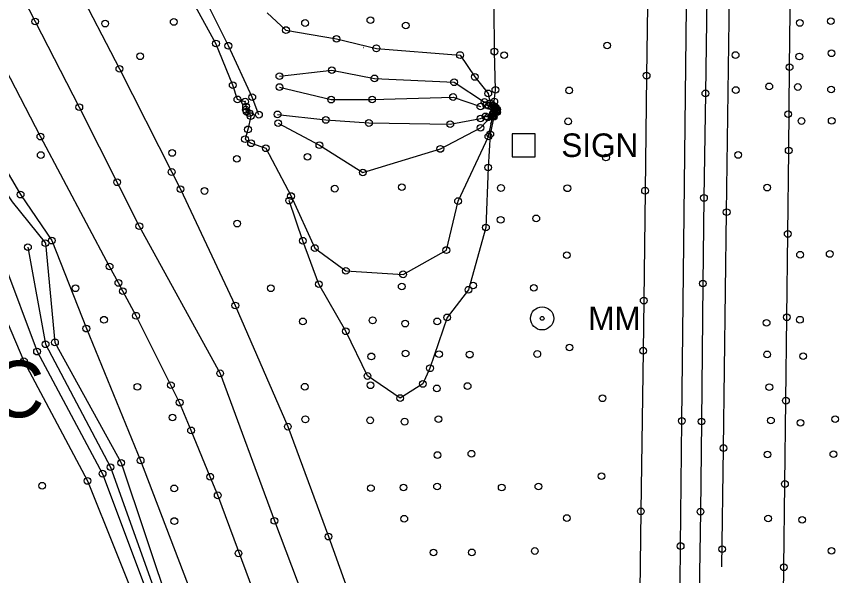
# Model space of a CAD drawing. Extents: x 20503438 to 20508873, y 7964251 to 7984667.
# Drawn here: x 20506434.7 to 20506679.2, y 7969674.2 to 7969840.4 of the extents above; entities that cross this region are included whole.
import ezdxf

# ---------------------------------------------------------------- set-up
doc = ezdxf.new("R2010")
doc.units = 0
for name, color, linetype in [('SurBreakLine', 7, 'Continuous'), ('SurConcreteSlab', 7, 'Continuous'), ('SurDrainageArrowDown', 7, 'Continuous'), ('SurDrainageArrowUp', 7, 'Continuous'), ('SurEdgeRoadPaved', 7, 'Continuous'), ('SurEdgeShoulderPaved', 7, 'Continuous'), ('SurGuardRailCable', 7, 'Continuous'), ('SurPointsNonDTM', 7, 'Continuous'), ('SurRoadPoints', 7, 'Continuous'), ('SurSurveyPoints', 7, 'Continuous'), ('SurTopOfWater', 7, 'Continuous'), ('SurTxtDrainage', 7, 'Continuous')]:
    doc.layers.add(name, color=color, linetype=linetype)

msp = doc.modelspace()

# ---------------------------------------------------------------- linework, layer by layer
at = {"layer": 'SurBreakLine'}
for points in [[(20506630.22, 7970500.51), (20506629.94, 7970458.31), (20506629.34, 7970411.54), (20506628.69, 7970380.29), (20506628.52, 7970349.87), (20506627.74, 7970284.03), (20506627.47, 7970249.09), (20506626.82, 7970216.67), (20506626.3, 7970146.74), (20506624.57, 7970007.29), (20506624.05, 7969973.48), (20506623.87, 7969953.25), (20506623.51, 7969921.12), (20506622.74, 7969871.31), (20506622.11, 7969822.83), (20506621.64, 7969788.61), (20506621.25, 7969755.93), (20506621.07, 7969741.02), (20506620.4, 7969693.27), (20506619.78, 7969645.95), (20506618.53, 7969549.76), (20506618.14, 7969523.36), (20506617.67, 7969481.03)], [(20506055.68, 7970391.77), (20506077.75, 7970359.75), (20506108.69, 7970301.09), (20506132.04, 7970256.55), (20506165.25, 7970205.48), (20506192.45, 7970157.41), (20506224.46, 7970101.44), (20506248.25, 7970061.27), (20506293.41, 7969992.66), (20506326.25, 7969942.44), (20506365.51, 7969880.7), (20506394.3, 7969832.14), (20506425.75, 7969780.09), (20506430.79, 7969767.57), (20506440.81, 7969740.77), (20506460.31, 7969704.46), (20506476.26, 7969661.89), (20506493.48, 7969607.85), (20506507.96, 7969563.39)], [(20506265.17, 7970071.99), (20506309.01, 7970002.39), (20506340.2, 7969952.07), (20506378, 7969886.15), (20506406.73, 7969836.94), (20506435.92, 7969787.45), (20506445.2, 7969773.78), (20506455.48, 7969747.6), (20506471.62, 7969708.42), (20506487.81, 7969665.88), (20506504.3, 7969609.54), (20506517.07, 7969565.09), (20506530.55, 7969501.87), (20506539.77, 7969458.14)], [(20506259.31, 7970069.25), (20506303.96, 7969999.09), (20506335.37, 7969948.79), (20506372.37, 7969884.24), (20506399.91, 7969834.73), (20506433.45, 7969785.26), (20506443.29, 7969773.02), (20506446.14, 7969743.51), (20506465.85, 7969707.69), (20506480.64, 7969663.58), (20506499.73, 7969608.5), (20506514.68, 7969564.41), (20506526.38, 7969501.4), (20506535.77, 7969458.35)], [(20506576.47, 7969813.92), (20506576.81, 7969815.09), (20506577.14, 7969818.61), (20506576.83, 7969829.97), (20506576.75, 7969843.33), (20506575.3, 7969863.86), (20506578.05, 7969884.56), (20506578.11, 7969925.71), (20506579.5, 7969969.66), (20506580.94, 7970015.91), (20506579.56, 7970061.86)], [(20506245.46, 7970059.26), (20506289.42, 7969989.86), (20506322.08, 7969939.84), (20506362.1, 7969878.45), (20506391.2, 7969829.89), (20506418.64, 7969776.17), (20506425.78, 7969763.92), (20506436.91, 7969737.91), (20506455.83, 7969702.3), (20506472.72, 7969660.29), (20506490.33, 7969606.63), (20506502.81, 7969561.31), (20506518.36, 7969500.09), (20506526.15, 7969455.03)], [(20506502.97, 7969813.65), (20506502.68, 7969815.08), (20506500.4, 7969815.76), (20506499.02, 7969820), (20506494.03, 7969832.4), (20506486.84, 7969845.43)], [(20506509.22, 7969841.54), (20506514.85, 7969836.38), (20506529.87, 7969833.76), (20506541.73, 7969830.94), (20506566.61, 7969828.95), (20506571.04, 7969822.43), (20506575.01, 7969817.54), (20506575.59, 7969814.64), (20506576.47, 7969813.92)], [(20506512.89, 7969822.68), (20506528.49, 7969824.45), (20506541.15, 7969822.01), (20506564.85, 7969820.86), (20506573.91, 7969814.98), (20506575.59, 7969814.64)], [(20506512.53, 7969808.7), (20506524.78, 7969802.14), (20506537.72, 7969794.01), (20506560.76, 7969801.03), (20506572.71, 7969807.3), (20506576.64, 7969811.43), (20506577.65, 7969811.98), (20506577.62, 7969812.72), (20506577.19, 7969813.47), (20506576.47, 7969813.92)], [(20506503.95, 7969811.65), (20506504.35, 7969810.81), (20506503.55, 7969806.83), (20506502.67, 7969803.92), (20506504.46, 7969802.72), (20506508.87, 7969801.23), (20506516.35, 7969787.02), (20506523.4, 7969771.55), (20506532.68, 7969764.79), (20506549.67, 7969763.74), (20506562.55, 7969770.96), (20506566.04, 7969785.52), (20506575.06, 7969804.72), (20506576.35, 7969810.79), (20506576.64, 7969811.43)], [(20506512.36, 7969811.29), (20506526.72, 7969809.66), (20506539.52, 7969808.75), (20506563.72, 7969808.41), (20506572.72, 7969810.1), (20506574.23, 7969810.71)], [(20506576.64, 7969811.43), (20506576.68, 7969810.56), (20506575.61, 7969805.43), (20506575, 7969795.51), (20506574.32, 7969777.67), (20506569.14, 7969759.17), (20506562.79, 7969750.93), (20506557.68, 7969735.8), (20506555.54, 7969731.15), (20506548.82, 7969726.94), (20506539.09, 7969733.51), (20506532.67, 7969746.81), (20506524.63, 7969760.83), (20506519.88, 7969773.73), (20506515.8, 7969785.66)]]:
    msp.add_lwpolyline(points, dxfattribs=at)
at = {"layer": 'SurConcreteSlab'}
for points in [[(20506312.48, 7970084.37), (20506343.03, 7970026.25), (20506361.37, 7969990.21), (20506379.77, 7969955.07), (20506398.31, 7969920.35), (20506410.28, 7969897), (20506440.24, 7969838.92), (20506453.38, 7969813.47), (20506471.23, 7969778.05), (20506495.26, 7969734.3), (20506511.4, 7969690.45), (20506526.3, 7969651.11), (20506541.85, 7969602.36), (20506553.45, 7969551.94), (20506564.49, 7969514.44), (20506574.01, 7969461.11)], [(20506502.97, 7969813.65), (20506502.9, 7969812.7), (20506503.12, 7969812.13), (20506503.95, 7969811.65)]]:
    msp.add_lwpolyline(points, dxfattribs=at)
msp.add_lwpolyline([(20506574.23, 7969810.71), (20506576.62, 7969811.64), (20506577.29, 7969812.12), (20506577.07, 7969813.1), (20506576.06, 7969813.56), (20506574.42, 7969814.11), (20506575.09, 7969813.89), (20506576.82, 7969813.61), (20506577.38, 7969813), (20506577.49, 7969812.41), (20506577.24, 7969811.87), (20506576.43, 7969811.46), (20506574.91, 7969810.43)], close=True, dxfattribs=at)
at = {"layer": 'SurDrainageArrowDown'}
msp.add_lwpolyline([(20506660.27, 7969478.45), (20506660.63, 7969503.23), (20506660.96, 7969528), (20506661.29, 7969552.77), (20506661.62, 7969577.54), (20506661.94, 7969602.32), (20506662.27, 7969627.09), (20506662.6, 7969651.86), (20506662.93, 7969676.63), (20506663.25, 7969701.4), (20506663.54, 7969726.18), (20506663.82, 7969750.97), (20506664.09, 7969775.76), (20506664.37, 7969800.55), (20506664.64, 7969825.33), (20506664.92, 7969850.12), (20506665.19, 7969874.91), (20506665.47, 7969899.7), (20506665.74, 7969924.48), (20506666.29, 7969949.48), (20506666.84, 7969974.47), (20506667.39, 7969999.46), (20506667.92, 7970023.56)], dxfattribs=at)
at = {"layer": 'SurDrainageArrowUp'}
for points in [[(20506506.8, 7969811.22), (20506504.83, 7969816.42), (20506497.71, 7969831.72), (20506490.19, 7969846.9), (20506487, 7969862.95), (20506473.82, 7969880.15), (20506462.67, 7969902.49), (20506454.28, 7969923.38)], [(20506512.92, 7969819.43), (20506528.29, 7969815.7), (20506540.49, 7969815.71), (20506564.54, 7969816.47), (20506572.67, 7969813.63)], [(20506438.1, 7969771.83), (20506443.35, 7969742.94), (20506462.68, 7969706.4), (20506478.32, 7969662.6), (20506496.28, 7969609.97), (20506512.32, 7969564.26), (20506521.33, 7969501.72), (20506530.41, 7969455.42), (20506542.25, 7969371.11), (20506545.39, 7969325.12), (20506547.61, 7969281.18), (20506550.51, 7969229.55), (20506551.89, 7969191.24), (20506551.28, 7969123.71), (20506552.43, 7969055.04)]]:
    msp.add_lwpolyline(points, dxfattribs=at)
at = {"layer": 'SurEdgeRoadPaved'}
for points in [[(20506631.32, 7969619.45), (20506631.68, 7969642.79), (20506632.12, 7969671.61), (20506632.23, 7969682.94), (20506632.59, 7969720.14), (20506634, 7969843.3), (20506635.85, 7969961.58), (20506636.59, 7970028.9), (20506637.95, 7970121.57), (20506639.37, 7970242.27), (20506639.5, 7970278.6), (20506640.61, 7970371.42), (20506641.91, 7970469.55), (20506641.82, 7970500.36)], [(20506352.99, 7970040.84), (20506374.32, 7969999.65), (20506390.57, 7969968.92), (20506409.06, 7969933.38), (20506428.12, 7969896.18), (20506452.11, 7969850.37), (20506465.31, 7969824.83), (20506480.86, 7969794.17), (20506483.46, 7969789.06), (20506499.78, 7969754.47), (20506515.4, 7969718.45), (20506527.51, 7969685.76), (20506540.05, 7969650.65), (20506551.47, 7969616.02), (20506560.28, 7969585.76), (20506569.39, 7969550.43), (20506574.82, 7969528.04), (20506577.29, 7969513.59), (20506582.94, 7969483.55), (20506590.54, 7969483.63), (20506595.61, 7969483.68)]]:
    msp.add_lwpolyline(points, dxfattribs=at)
at = {"layer": 'SurEdgeShoulderPaved'}
for points in [[(20506648.62, 7970500.27), (20506647.27, 7970459.01), (20506646.9, 7970417.14), (20506644.76, 7970214.42), (20506643.68, 7970120.75), (20506642.88, 7970059), (20506642.28, 7970020.9), (20506641.72, 7969970.09), (20506641.45, 7969947.33), (20506640.93, 7969913.12), (20506640.56, 7969882.02), (20506639.59, 7969817.55), (20506639.17, 7969786.45), (20506638.82, 7969761), (20506638.43, 7969719.99), (20506638.13, 7969693.16), (20506637.46, 7969650.51), (20506637.08, 7969619.38)], [(20506558.41, 7969475.22), (20506553.3, 7969503.59), (20506539.73, 7969558.73), (20506532.5, 7969585.43), (20506523.93, 7969613.45), (20506515.14, 7969640.57), (20506505.25, 7969669.25), (20506494.55, 7969698.03), (20506492.29, 7969703.55), (20506486.63, 7969717.33), (20506483.23, 7969725.6), (20506480.64, 7969730.77), (20506470.25, 7969751.44), (20506466.32, 7969758.75), (20506465.01, 7969761.19), (20506462.39, 7969766.06), (20506441.81, 7969804.7), (20506420.97, 7969844.98)]]:
    msp.add_lwpolyline(points, dxfattribs=at)
at = {"layer": 'SurGuardRailCable'}
msp.add_lwpolyline([(20506644.52, 7969676.78), (20506644.99, 7969712.07), (20506645.92, 7969782.21), (20506647.25, 7969882.2), (20506647.95, 7969934.67), (20506648.41, 7969968.7), (20506648.87, 7970002.73), (20506649.33, 7970036.76), (20506649.78, 7970070.78), (20506650.7, 7970138.84), (20506651.16, 7970172.87), (20506651.48, 7970224.98), (20506652.13, 7970324.97), (20506653.06, 7970424.97), (20506653.71, 7970473.92), (20506653.91, 7970489.08), (20506654.11, 7970504.24), (20506654.31, 7970519.4), (20506654.51, 7970534.56), (20506654.91, 7970564.88), (20506655.11, 7970580.04), (20506656.2, 7970643.55), (20506657.97, 7970743.53), (20506658.92, 7970797.12)], dxfattribs=at)
at = {"layer": 'SurPointsNonDTM'}
for centre in [(20506664.23, 7969811.37), (20506464.65, 7969791.11), (20506645.92, 7969782.21), (20506644.99, 7969712.07), (20506644.59, 7969682.01)]:
    msp.add_circle(centre, 1, dxfattribs=at)
at = {"layer": 'SurRoadPoints'}
msp.add_lwpolyline([(20506585.54, 7969798.71), (20506585.54, 7969798.71), (20506588.97, 7969798.71), (20506588.97, 7969805.57), (20506582.11, 7969805.57), (20506582.11, 7969798.71), (20506585.54, 7969798.71)], dxfattribs=at)
for radius in [3.43, 0.571]:
    msp.add_circle((20506591.04, 7969750.64), radius, dxfattribs=at)
at = {"layer": 'SurSurveyPoints'}
for centre in [(20506440.24, 7969838.92), (20506461.08, 7969838.29), (20506481.47, 7969838.8), (20506520.53, 7969838.47), (20506539.96, 7969839.31), (20506667.68, 7969838.49), (20506676.92, 7969839.04), (20506514.85, 7969836.38), (20506550.47, 7969837.72), (20506529.87, 7969833.76), (20506494.03, 7969832.4), (20506497.71, 7969831.72), (20506541.73, 7969830.94), (20506610.36, 7969831.78), (20506471.49, 7969828.58), (20506566.61, 7969828.95), (20506576.83, 7969829.97), (20506579.75, 7969828.91), (20506648.58, 7969828.94), (20506667.54, 7969828.51), (20506677.1, 7969829.48), (20506465.31, 7969824.83), (20506528.49, 7969824.45), (20506664.64, 7969825.33), (20506512.89, 7969822.68), (20506541.15, 7969822.01), (20506571.04, 7969822.43), (20506622.11, 7969822.83), (20506499.02, 7969820), (20506512.92, 7969819.43), (20506564.85, 7969820.86), (20506577.14, 7969818.61), (20506658.59, 7969819.62), (20506667.08, 7969819.45), (20506676.98, 7969818.69), (20506504.83, 7969816.42), (20506564.54, 7969816.47), (20506575.01, 7969817.54), (20506599.06, 7969818.43), (20506639.59, 7969817.55), (20506648.62, 7969818.53), (20506500.4, 7969815.76), (20506502.68, 7969815.08), (20506528.29, 7969815.7), (20506540.49, 7969815.71), (20506573.91, 7969814.98), (20506574.42, 7969814.11), (20506575.09, 7969813.89), (20506575.59, 7969814.64), (20506576.47, 7969813.92), (20506576.81, 7969815.09), (20506453.38, 7969813.47), (20506502.9, 7969812.7), (20506502.97, 7969813.65), (20506503.12, 7969812.13), (20506503.95, 7969811.65), (20506512.36, 7969811.29), (20506572.67, 7969813.63), (20506576.06, 7969813.56), (20506576.43, 7969811.46), (20506576.62, 7969811.64), (20506576.64, 7969811.43), (20506576.82, 7969813.61), (20506577.07, 7969813.1), (20506577.19, 7969813.47), (20506577.24, 7969811.87), (20506577.29, 7969812.12), (20506577.38, 7969813), (20506577.49, 7969812.41), (20506577.62, 7969812.72), (20506577.65, 7969811.98), (20506504.35, 7969810.81), (20506506.8, 7969811.22), (20506526.72, 7969809.66), (20506572.72, 7969810.1), (20506574.23, 7969810.71), (20506574.91, 7969810.43), (20506576.35, 7969810.79), (20506576.68, 7969810.56), (20506598.78, 7969809.23), (20506668.18, 7969809.34), (20506677.16, 7969809.4), (20506503.55, 7969806.83), (20506512.53, 7969808.7), (20506539.52, 7969808.75), (20506563.72, 7969808.41), (20506572.71, 7969807.3), (20506441.81, 7969804.7), (20506575.06, 7969804.72), (20506575.61, 7969805.43), (20506502.67, 7969803.92), (20506504.46, 7969802.72), (20506524.78, 7969802.14), (20506441.91, 7969799.21), (20506480.99, 7969799.84), (20506508.87, 7969801.23), (20506560.76, 7969801.03), (20506649.33, 7969799.25), (20506664.37, 7969800.55), (20506500.23, 7969798.08), (20506521.25, 7969798.67), (20506610.03, 7969798.49), (20506480.86, 7969794.17), (20506575, 7969795.51), (20506537.72, 7969794.01), (20506549.29, 7969789.68), (20506578.8, 7969789.42), (20506598.54, 7969789.34), (20506657.95, 7969789.54), (20506435.92, 7969787.45), (20506483.46, 7969789.06), (20506490.63, 7969788.53), (20506516.35, 7969787.02), (20506529.36, 7969789.21), (20506621.64, 7969788.61), (20506515.8, 7969785.66), (20506566.04, 7969785.52), (20506639.17, 7969786.45), (20506578.71, 7969779.95), (20506589.29, 7969780.38), (20506471.23, 7969778.05), (20506500.32, 7969778.82), (20506574.32, 7969777.67), (20506664.09, 7969775.76), (20506443.29, 7969773.02), (20506445.2, 7969773.78), (20506519.88, 7969773.73), (20506438.1, 7969771.83), (20506523.4, 7969771.55), (20506562.55, 7969770.96), (20506676.57, 7969769.8), (20506598.37, 7969769.44), (20506667.75, 7969769.57), (20506462.39, 7969766.06), (20506532.68, 7969764.79), (20506549.67, 7969763.74), (20506465.01, 7969761.19), (20506524.63, 7969760.83), (20506549.28, 7969760.12), (20506570.54, 7969760.43), (20506638.82, 7969761), (20506452.24, 7969759.59), (20506466.32, 7969758.75), (20506510.34, 7969759.6), (20506569.14, 7969759.17), (20506588.56, 7969759.72), (20506621.25, 7969755.93), (20506499.78, 7969754.47), (20506460.72, 7969750.24), (20506470.25, 7969751.44), (20506562.79, 7969750.93), (20506663.82, 7969750.97), (20506667.72, 7969750.25), (20506519.89, 7969749.74), (20506540.63, 7969750.06), (20506550.3, 7969749.08), (20506559.85, 7969749.74), (20506657.79, 7969749.33), (20506455.48, 7969747.6), (20506532.67, 7969746.81), (20506443.35, 7969742.94), (20506446.14, 7969743.51), (20506440.81, 7969740.77), (20506599.16, 7969741.97), (20506621.07, 7969741.02), (20506540.24, 7969739.34), (20506550.42, 7969740.22), (20506560.37, 7969740.01), (20506569.48, 7969739.88), (20506589.6, 7969740.05), (20506657.98, 7969739.94), (20506668.68, 7969739.42), (20506436.91, 7969737.91), (20506557.68, 7969735.8), (20506495.26, 7969734.3), (20506539.09, 7969733.51), (20506480.64, 7969730.77), (20506539.98, 7969730.75), (20506555.54, 7969731.15), (20506470.65, 7969730.27), (20506520.43, 7969730.32), (20506559.73, 7969729.83), (20506568.87, 7969730.52), (20506658.61, 7969730.2), (20506548.82, 7969726.94), (20506609.01, 7969726.88), (20506663.54, 7969726.18), (20506483.23, 7969725.6), (20506481.1, 7969721.15), (20506515.4, 7969718.45), (20506520.61, 7969720.63), (20506539.87, 7969720.33), (20506550.14, 7969719.93), (20506560.18, 7969720.68), (20506632.59, 7969720.14), (20506638.43, 7969719.99), (20506659.08, 7969720.29), (20506667.89, 7969719.59), (20506678.2, 7969720.67), (20506486.63, 7969717.33), (20506559.92, 7969710), (20506570, 7969710.39), (20506658.07, 7969710.17), (20506677.66, 7969710.28), (20506462.68, 7969706.4), (20506465.85, 7969707.69), (20506471.62, 7969708.42), (20506460.31, 7969704.46), (20506608.71, 7969703.72), (20506455.83, 7969702.3), (20506492.29, 7969703.55), (20506663.25, 7969701.4), (20506442.34, 7969700.87), (20506481.62, 7969700.08), (20506540.12, 7969700.14), (20506549.82, 7969700.37), (20506559.79, 7969700.65), (20506579.01, 7969700.36), (20506589.92, 7969700.64), (20506494.55, 7969698.03), (20506620.4, 7969693.27), (20506638.13, 7969693.16), (20506481.65, 7969690.37), (20506511.4, 7969690.45), (20506550.03, 7969691.06), (20506598.37, 7969691.27), (20506658.24, 7969691.13), (20506668.37, 7969690.74), (20506527.51, 7969685.76), (20506632.23, 7969682.94), (20506500.73, 7969680.77), (20506558.74, 7969681.03), (20506570.13, 7969681.05), (20506588.86, 7969681.47), (20506677.12, 7969681.52), (20506662.93, 7969676.63)]:
    msp.add_circle(centre, 1, dxfattribs=at)
at = {"layer": 'SurTopOfWater'}
for points in [[(20506537.84, 7969831.18), (20506537.88, 7969831.18), (20506537.88, 7969831.22), (20506537.84, 7969831.22)], [(20506537.86, 7969831.23), (20506537.86, 7969831.23), (20506537.86, 7969831.19), (20506537.86, 7969831.19)], [(20506537.86, 7969831.23), (20506537.86, 7969831.23), (20506537.86, 7969831.21), (20506537.86, 7969831.21)], [(20506537.86, 7969831.21), (20506537.86, 7969831.21), (20506537.86, 7969831.2), (20506537.86, 7969831.2)], [(20506537.86, 7969831.2), (20506537.86, 7969831.2), (20506537.86, 7969831.19), (20506537.86, 7969831.19)], [(20506502.76, 7969815.08), (20506502.8, 7969815.08), (20506502.8, 7969815.12), (20506502.76, 7969815.12)], [(20506502.78, 7969815.13), (20506502.78, 7969815.13), (20506502.78, 7969815.09), (20506502.78, 7969815.09)], [(20506502.78, 7969815.13), (20506502.78, 7969815.13), (20506502.78, 7969815.11), (20506502.78, 7969815.11)], [(20506502.78, 7969815.11), (20506502.78, 7969815.11), (20506502.78, 7969815.1), (20506502.78, 7969815.1)], [(20506502.78, 7969815.1), (20506502.78, 7969815.1), (20506502.78, 7969815.09), (20506502.78, 7969815.09)], [(20506575.71, 7969808.63), (20506575.75, 7969808.63), (20506575.75, 7969808.67), (20506575.71, 7969808.67)], [(20506575.73, 7969808.68), (20506575.73, 7969808.68), (20506575.73, 7969808.64), (20506575.73, 7969808.64)], [(20506575.73, 7969808.68), (20506575.73, 7969808.68), (20506575.73, 7969808.66), (20506575.73, 7969808.66)], [(20506575.73, 7969808.66), (20506575.73, 7969808.66), (20506575.73, 7969808.65), (20506575.73, 7969808.65)], [(20506575.73, 7969808.65), (20506575.73, 7969808.65), (20506575.73, 7969808.64), (20506575.73, 7969808.64)]]:
    msp.add_lwpolyline(points, close=True, dxfattribs=at)
for centre in [(20506537.85, 7969831.2), (20506537.86, 7969831.2), (20506537.87, 7969831.2), (20506502.77, 7969815.1), (20506502.78, 7969815.1), (20506502.79, 7969815.1), (20506575.72, 7969808.65), (20506575.73, 7969808.65), (20506575.74, 7969808.65)]:
    msp.add_arc(centre, 0.00586, 186.3566, 5.6839, dxfattribs=at)

# ---------------------------------------------------------------- texts
at = {"layer": 'SurRoadPoints'}
for s, p in [('SIGN', (20506596.75, 7969798.64)), ('MM', (20506604.75, 7969747.14))]:
    msp.add_text(s, height=6.995, rotation=360, dxfattribs=at).set_placement(p)
at = {"layer": 'SurTxtDrainage'}
msp.add_text('= Sta. 4370+00 Ramp C', height=16.8, dxfattribs=at).set_placement((20506200.73, 7969721.22))

doc.saveas('drawing.dxf')
